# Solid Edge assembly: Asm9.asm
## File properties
Author: Cadcim
Template: Iso Assembly.asm
Last saved by: Cadcim
Revision: 1
Application: Solid Edge
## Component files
support_roller_bracket.par
adjusting_screw_nut.par
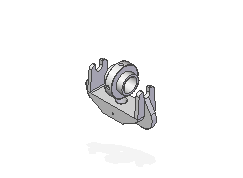
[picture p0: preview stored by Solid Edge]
